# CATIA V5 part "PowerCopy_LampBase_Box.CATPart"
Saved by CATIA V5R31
Part number: LampBase_Box
Bounding box of the stored display mesh (mm): x -20 to 20, y -20 to 20, z 0 to 20
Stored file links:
  C:\Users\patol451\OneDrive - Linköpings universitet\Nuvarande kurser\Exjobb\LampCATIA\PowerCopy_LampBase_Box.CATPart
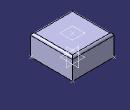
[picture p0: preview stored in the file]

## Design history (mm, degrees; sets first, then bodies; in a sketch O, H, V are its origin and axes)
Parameters
  radius = 2 mm
Set1 "References"
  Point1 "P1": (20, 20, 0)
  Point2 "P2": (20, -20, 0)
  Point3 "P3": (-20, -20, 0)
  Point4 "P4": (-20, 20, 0)
  Plane1 "BaseHeightPlane": type Offset, RefPlane xy-plane, Offset 20
Set2 "Geo1"
  Line1: type PtPt, FirstPoint Point3, SecondPoint Point4
  Line2: type PtPt, FirstPoint Point4, SecondPoint Point1
  Line3: type PtPt, FirstPoint Point1, SecondPoint Point2
  Line4: type PtPt, FirstPoint Point2, SecondPoint Point3
  Join1: Elements (Line1; Line2; Line3; Line4)
Set3 "OutputSupport"
  Line5: type PtPt, FirstPoint Point3, SecondPoint Point1
  Line6: type PtPt, FirstPoint Point2, SecondPoint Point4
  Intersect1: ToIntersect1 Line6, ToIntersect2 Line5
Set4 "Output"
  Project1 "OutputPoint1": ToProject Intersect1, Support Plane1
Set5 "Placement"
  Intersect2 "PlacementPoint": ToIntersect1 Line6, ToIntersect2 Line5
Body1 (main body)
  Pad1: profile Join1, up to Plane1
  Fillet1: radius 2 {= radius}, on end face of Pad1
